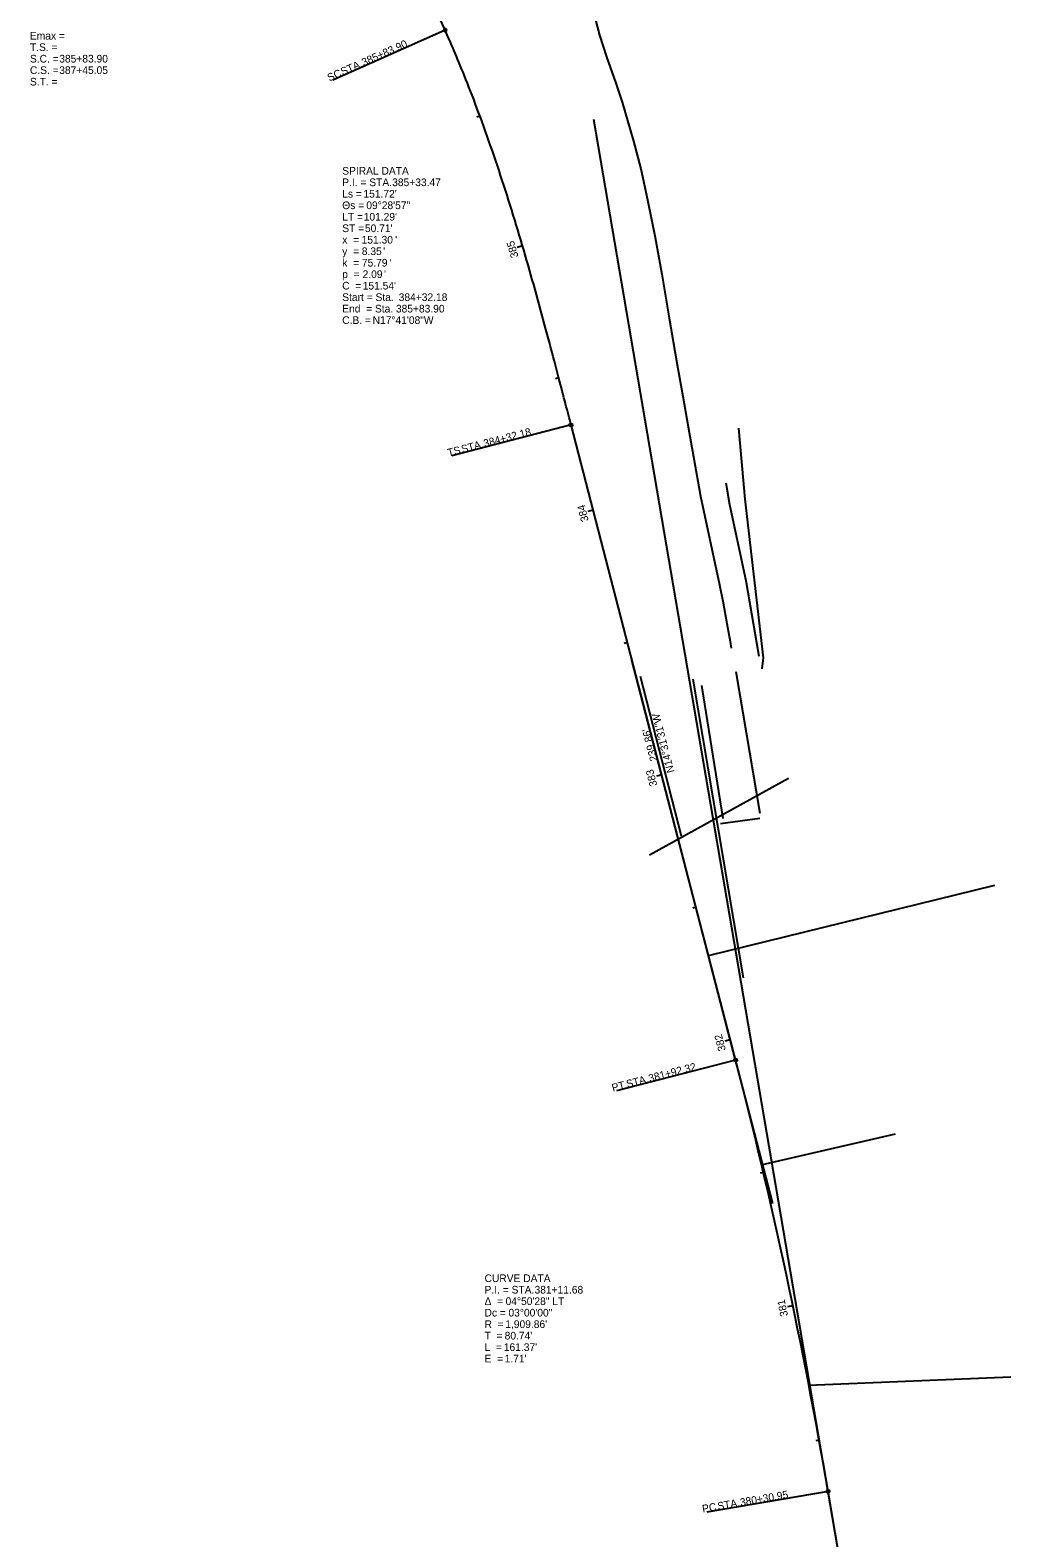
# Model space of a CAD drawing. Extents: x 111442 to 112326, y 429427 to 431077.
# Drawn here: x 111923 to 112281, y 430040 to 430591 of the extents above; entities that cross this region are included whole.
import ezdxf

# ---------------------------------------------------------------- set-up
doc = ezdxf.new("R2010")
doc.units = 0
for name, color, linetype in [('GE_P_Alignment', 7, 'Continuous'), ('GE_P_Alignment_100_Bearings', 7, 'Continuous'), ('GE_P_Alignment_100_Cardinal_Points', 7, 'Continuous'), ('GE_P_Alignment_100_Curve_Data', 7, 'Continuous'), ('GE_P_Alignment_100_Distances', 7, 'Continuous'), ('GE_P_Alignment_100_Stations', 7, 'Continuous'), ('SC_Scratch10', 7, 'Continuous'), ('SC_Scratch4', 7, 'Continuous'), ('SC_Scratch6', 7, 'Continuous')]:
    doc.layers.add(name, color=color, linetype=linetype)

msp = doc.modelspace()

# ---------------------------------------------------------------- linework, layer by layer
at = {"layer": 'GE_P_Alignment'}
for p, q in [((112253.32, 429829.29), (112128.86, 430558.62)), ((112180.64, 430214.69), (112120.49, 430446.88)), ((112194.24, 430162.2), (112142.77, 430360.87)), ((112253.32, 429829.29), (112214.47, 430056.95))]:
    msp.add_line(p, q, dxfattribs=at)
for centre, radius, start, end in [((111655.73, 430404.76), 458.37, 24.0078, 44.1517), ((111655.73, 430404.76), 458.37, 24.0078, 44.1517), ((110331.83, 429735.68), 1909.86, 9.68414, 14.52537), ((110331.83, 429735.68), 1909.86, 9.68414, 14.52537)]:
    msp.add_arc(centre, radius, start, end, dxfattribs=at)
msp.add_open_spline([(112120.49, 430446.88), (112119.85, 430449.33), (112118.58, 430454.22), (112116.04, 430464.01), (112112.83, 430476.24), (112108.87, 430490.89), (112104.78, 430505.5), (112100.49, 430520.05), (112095.96, 430534.53), (112091.14, 430548.92), (112085.99, 430563.2), (112081.39, 430574.97), (112077.5, 430584.31), (112075.48, 430588.94), (112074.45, 430591.25)], degree=3, dxfattribs=at)
msp.add_open_spline([(112120.49, 430446.88), (112119.85, 430449.33), (112118.58, 430454.22), (112116.04, 430464.01), (112112.83, 430476.24), (112108.87, 430490.89), (112104.78, 430505.5), (112100.49, 430520.05), (112095.96, 430534.53), (112091.14, 430548.92), (112085.99, 430563.2), (112081.39, 430574.97), (112077.5, 430584.31), (112075.48, 430588.94), (112074.45, 430591.25)], degree=3, dxfattribs=at)
at = {"layer": 'GE_P_Alignment_100_Cardinal_Points'}
for p, q in [((112074.45, 430591.25), (112033.34, 430572.95)), ((112120.49, 430446.88), (112076.92, 430435.59)), ((112180.64, 430214.69), (112137.08, 430203.4)), ((112214.47, 430056.95), (112170.12, 430049.38))]:
    msp.add_line(p, q, dxfattribs=at)
for centre in [(112074.45, 430591.25), (112120.49, 430446.88), (112180.64, 430214.69), (112214.47, 430056.95)]:
    msp.add_circle(centre, 0.6, dxfattribs=at)
at = {"layer": 'GE_P_Alignment_100_Distances'}
for p, q in [((112184.2, 430419.71), (112181.78, 430445.77)), ((112178.5, 430417.73), (112177.23, 430425.64)), ((112184.56, 430389.91), (112178.5, 430417.73)), ((112190.9, 430361.79), (112184.2, 430419.71)), ((112189.27, 430362.22), (112184.56, 430389.91)), ((112190.39, 430357.7), (112190.9, 430361.79))]:
    msp.add_line(p, q, dxfattribs=at)
at = {"layer": 'GE_P_Alignment_100_Stations'}
for p, q in [((112087.17, 430559.84), (112086.05, 430559.42)), ((112102.75, 430512.34), (112100.84, 430511.77)), ((112116, 430464.13), (112114.84, 430463.82)), ((112128.56, 430415.73), (112126.62, 430415.23)), ((112141.1, 430367.33), (112139.93, 430367.03)), ((112153.64, 430318.93), (112151.7, 430318.42)), ((112166.18, 430270.52), (112165.02, 430270.22)), ((112178.72, 430222.12), (112176.78, 430221.62)), ((112190.8, 430173.61), (112189.64, 430173.33)), ((112201.63, 430124.79), (112199.67, 430124.39)), ((112211.18, 430075.71), (112209.99, 430075.5))]:
    msp.add_line(p, q, dxfattribs=at)
at = {"layer": 'SC_Scratch10'}
for p, q in [((112160.87, 430296.48), (112145.94, 430354.86)), ((112183.56, 430244.72), (112165.08, 430353.93)), ((112176.06, 430302.99), (112168.35, 430351.68)), ((112189.6, 430304.88), (112180.85, 430356.6)), ((112149.23, 430289.77), (112199.98, 430317.8)), ((112175.17, 430301.12), (112189.51, 430303.09))]:
    msp.add_line(p, q, dxfattribs=at)
at = {"layer": 'SC_Scratch4'}
for p, q in [((112170.74, 430252.93), (112275.39, 430278.65)), ((112190.02, 430176.32), (112239.16, 430187.73)), ((112207.29, 430095.79), (112281.31, 430098.87))]:
    msp.add_line(p, q, dxfattribs=at)
at = {"layer": 'SC_Scratch6'}
msp.add_lwpolyline([(112129.39, 430595.01), (112130.93, 430589.43), (112133.49, 430581.56), (112136.91, 430571.81), (112139.2, 430564.96), (112143.37, 430550.71), (112145.95, 430540.49), (112148.47, 430529.25), (112151.24, 430515.38), (112153.64, 430502.04), (112156.27, 430486.72), (112159.33, 430468.94), (112161.33, 430457.48), (112163.27, 430446.24), (112167.8, 430420.85), (112172.02, 430401.43), (112174.63, 430389.06), (112176.07, 430381.84), (112177.5, 430374.24), (112178.66, 430367.7), (112179.07, 430365.28)], dxfattribs=at)

# ---------------------------------------------------------------- texts
at = {"layer": 'GE_P_Alignment_100_Bearings'}
msp.add_text('N14°31\'31"W', height=2.8, rotation=104.5254, dxfattribs=at).set_placement((112158.3, 430320.07))
at = {"layer": 'GE_P_Alignment_100_Cardinal_Points'}
for s, rotation, p in [('385+83.90', 24.0078, (112044.66, 430578.03)), (' STA. ', 24.0078, (112036.02, 430574.19)), ('SC', 24.0078, (112032.09, 430572.44)), ('384+32.18', 14.5254, (112088.86, 430438.73)), (' STA. ', 14.5254, (112079.71, 430436.36)), ('TS', 14.5254, (112075.69, 430435.32)), ('381+92.32', 14.5254, (112149.2, 430206.58)), (' STA. ', 14.5254, (112140.05, 430204.21)), ('PT', 14.5254, (112135.78, 430203.11)), (' STA. ', 9.6841, (112173.2, 430049.95)), ('380+30.95', 9.6841, (112182.52, 430051.54)), ('PC', 9.6841, (112168.68, 430049.18))]:
    msp.add_text(s, height=2.8, rotation=rotation, dxfattribs=at).set_placement(p)
at = {"layer": 'GE_P_Alignment_100_Curve_Data'}
for s, rotation, p in [('Emax = ', 360, (111922.61, 430587.82)), ('T.S. = ', 360, (111922.61, 430583.62)), ('S.C. = ', 360, (111922.61, 430579.42)), ('C.S. = ', 360, (111922.61, 430575.22)), ('385+83.90', 360, (111933.33, 430579.42)), ('387+45.05', 360, (111933.33, 430575.22)), ('S.T. = ', 360, (111922.61, 430571.02)), ('SPIRAL DATA', 0.0003, (112036.81, 430538.42)), ('P.I. = STA. ', 0.0003, (112036.81, 430534.22)), ('385+33.47', 0.0003, (112055.07, 430534.22)), ('Θs = ', 0.0003, (112036.81, 430525.82)), ('Ls = ', 0.0003, (112036.81, 430530.02)), ("151.72'", 0.0003, (112044.57, 430530.02)), ('09°28\'57"', 0.0003, (112045.61, 430525.82)), ('LT = ', 0.0003, (112036.81, 430521.62)), ("101.29'", 0.0003, (112044.66, 430521.62)), ('ST = ', 0.0003, (112036.81, 430517.42)), ("50.71'", 0.0003, (112045.11, 430517.42)), ('y  = ', 0.0003, (112036.81, 430509.02)), ('x  = ', 0.0003, (112036.81, 430513.22)), ('8.35', 0.0003, (112043.97, 430509.02)), ('151.30', 0.0003, (112043.9, 430513.22)), ("'", 0.0003, (112051.79, 430509.02)), ("'", 0.0003, (112056.19, 430513.22)), ('k  = ', 0.0003, (112036.81, 430504.82)), ('75.79', 0.0003, (112044, 430504.82)), ("'", 0.0003, (112054.05, 430504.82)), ('p  = ', 0.0003, (112036.81, 430500.62)), ('2.09', 0.0003, (112044.26, 430500.62)), ("'", 0.0003, (112052.08, 430500.62)), ('Start = Sta. ', 0.0003, (112036.81, 430492.22)), ('C  = ', 0.0003, (112036.81, 430496.42)), ("151.54'", 0.0003, (112044.3, 430496.42)), ('384+32.18', 0.0003, (112057.46, 430492.22)), ('End  = Sta. ', 0.0003, (112036.81, 430488.02)), ('385+83.90', 0.0003, (112056.44, 430488.02)), ('C.B. = ', 0.0003, (112036.81, 430483.82)), ('N17°41\'08"W', 0.0003, (112047.93, 430483.82)), ('CURVE DATA', 360, (112088.86, 430133.5)), ('P.I. = STA. ', 360, (112088.86, 430129.3)), ('381+11.68', 360, (112107.13, 430129.3)), ('Δ  = ', 360, (112088.86, 430125.1)), ('04°50\'28" LT', 360, (112096.54, 430125.1)), ('Dc = ', 360, (112088.86, 430120.9)), ('03°00\'00"', 360, (112097.6, 430120.9)), ('T  = ', 360, (112088.86, 430112.5)), ('R  = ', 360, (112088.86, 430116.7)), ("80.74'", 360, (112096.2, 430112.5)), ("1,909.86'", 360, (112096.44, 430116.7)), ('L  = ', 360, (112088.86, 430108.3)), ("161.37'", 360, (112095.9, 430108.3)), ('E  = ', 360, (112088.86, 430104.1)), ("1.71'", 360, (112096.2, 430104.1))]:
    msp.add_text(s, height=2.8, rotation=rotation, dxfattribs=at).set_placement(p)
at = {"layer": 'GE_P_Alignment_100_Distances'}
msp.add_text("239.86'", height=2.8, rotation=104.5254, dxfattribs=at).set_placement((112152.2, 430324.31))
at = {"layer": 'GE_P_Alignment_100_Stations'}
for s, rotation, p in [('385', 106.4201, (112101.29, 430508.46)), ('384', 104.5254, (112126.96, 430411.93)), ('383', 104.5254, (112152.04, 430315.13)), ('382', 104.5254, (112177.12, 430218.32)), ('381', 101.7558, (112199.82, 430121.2))]:
    msp.add_text(s, height=2.8, rotation=rotation, dxfattribs=at).set_placement(p)

doc.saveas('drawing.dxf')
